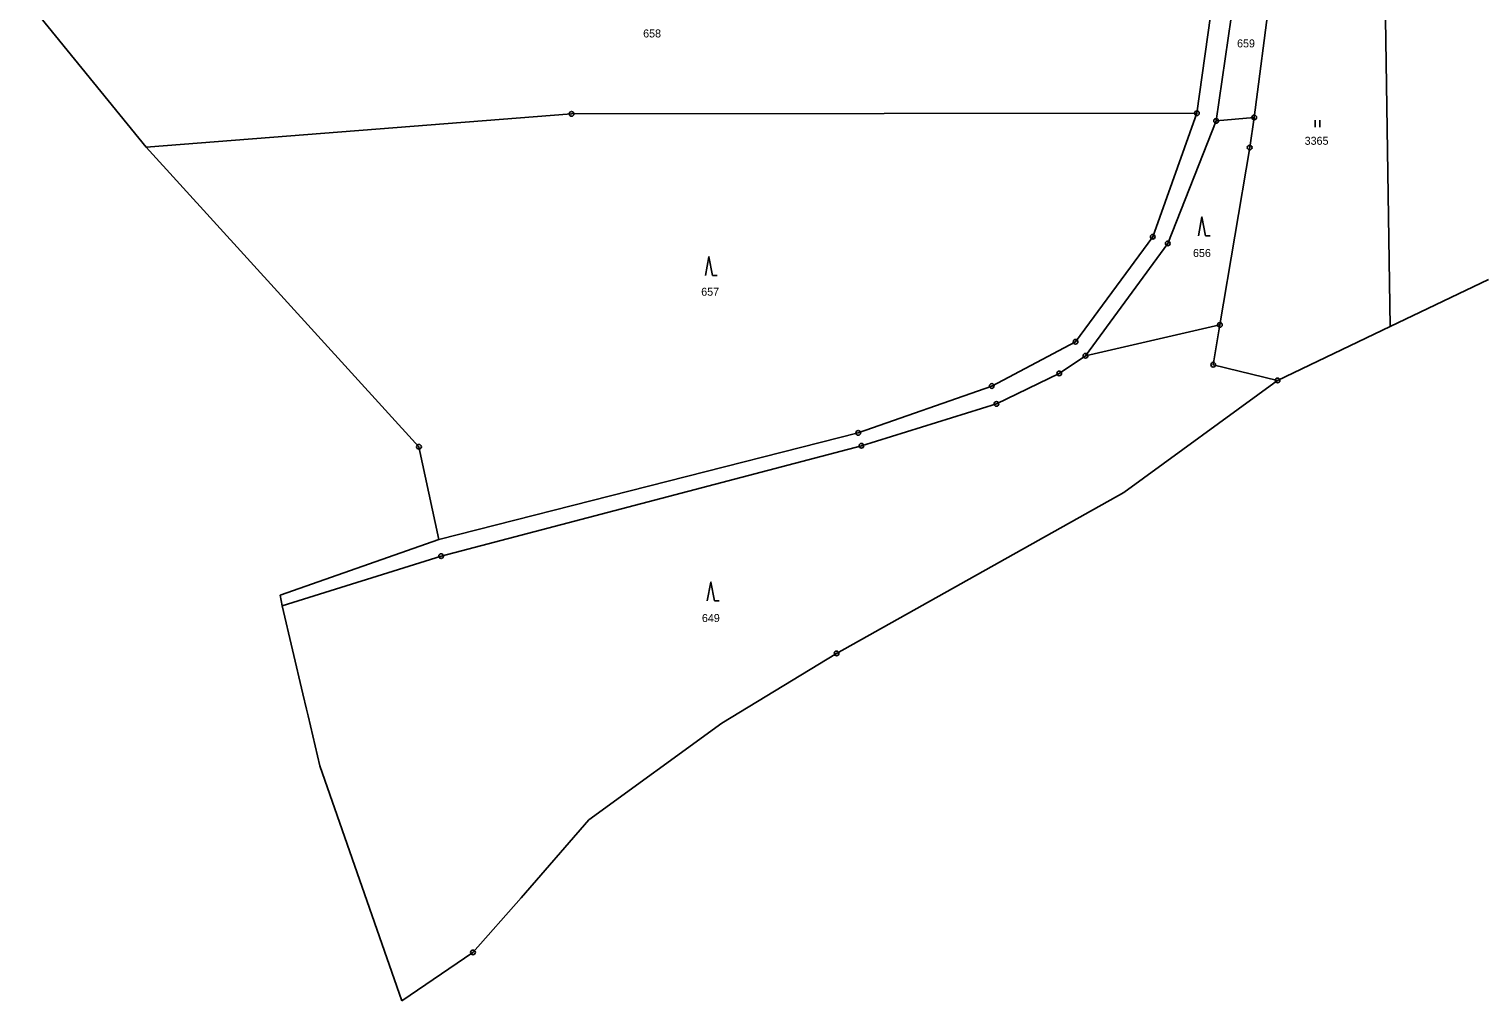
# Model space of a CAD drawing. Extents: x -618848 to -615803, y -1044450 to -1042254.
# Drawn here: x -618808.6 to -618500.4, y -1044247.6 to -1044041.1 of the extents above; entities that cross this region are included whole.
import ezdxf
from ezdxf.enums import TextEntityAlignment as Align

# ---------------------------------------------------------------- set-up
doc = ezdxf.new("R2010")
doc.units = 0
doc.header["$LTSCALE"] = 0.68
for name, color, linetype, lineweight in [('1', 7, 'Continuous', 25), ('3', 7, 'Continuous', 25), ('8', 7, 'Continuous', 25)]:
    doc.layers.add(name, color=color, linetype=linetype, lineweight=lineweight)
doc.layers.add('2', color=7, linetype='Continuous')

msp = doc.modelspace()

# ---------------------------------------------------------------- linework, layer by layer
at = {"layer": '1'}
for p, q in [((-618521.01, -1044002.05), (-618519.5, -1044104.29)), ((-618560.52, -1044058.97), (-618555.21, -1044021.21)), ((-618556.45, -1044060.6), (-618550.93, -1044022.46)), ((-618543.72, -1044024.32), (-618548.36, -1044059.86)), ((-618808.59, -1044035.66), (-618783.68, -1044066.18)), ((-618783.68, -1044066.18), (-618693.34, -1044059.1)), ((-618693.34, -1044059.1), (-618560.52, -1044058.97)), ((-618560.52, -1044058.97), (-618569.91, -1044085.21)), ((-618566.73, -1044086.63), (-618556.45, -1044060.6)), ((-618556.45, -1044060.6), (-618548.36, -1044059.86)), ((-618548.36, -1044059.86), (-618549.32, -1044066.26)), ((-618783.68, -1044066.18), (-618725.76, -1044129.84)), ((-618549.32, -1044066.26), (-618555.64, -1044103.94)), ((-618569.91, -1044085.21), (-618586.31, -1044107.53)), ((-618584.19, -1044110.49), (-618566.73, -1044086.63)), ((-618498.61, -1044094.27), (-618519.5, -1044104.29)), ((-618584.19, -1044110.49), (-618555.64, -1044103.94)), ((-618555.64, -1044103.94), (-618557.07, -1044112.39)), ((-618543.38, -1044115.75), (-618519.5, -1044104.29)), ((-618586.31, -1044107.53), (-618604.1, -1044116.92)), ((-618589.77, -1044114.24), (-618584.19, -1044110.49)), ((-618557.07, -1044112.39), (-618543.38, -1044115.75)), ((-618604.1, -1044116.92), (-618632.46, -1044126.87)), ((-618603.1, -1044120.73), (-618589.77, -1044114.24)), ((-618576.05, -1044139.52), (-618543.38, -1044115.75)), ((-618631.79, -1044129.6), (-618603.1, -1044120.73)), ((-618632.46, -1044126.87), (-618721.57, -1044149.5)), ((-618725.76, -1044129.84), (-618721.57, -1044149.5)), ((-618721.07, -1044153.07), (-618631.79, -1044129.6)), ((-618755.25, -1044161.39), (-618721.57, -1044149.5)), ((-618754.79, -1044163.6), (-618721.07, -1044153.07)), ((-618755.25, -1044161.39), (-618754.79, -1044163.6)), ((-618754.79, -1044163.6), (-618750.4, -1044182.33)), ((-618750.4, -1044182.33), (-618749.64, -1044185.58)), ((-618749.64, -1044185.58), (-618749.3, -1044187.02)), ((-618749.3, -1044187.02), (-618746.81, -1044197.63)), ((-618689.7, -1044209.09), (-618661.45, -1044188.56)), ((-618746.81, -1044197.63), (-618729.38, -1044247.57)), ((-618689.7, -1044209.09), (-618704.07, -1044225.65)), ((-618704.07, -1044225.65), (-618714.29, -1044237.24)), ((-618714.29, -1044237.24), (-618729.38, -1044247.57))]:
    msp.add_line(p, q, dxfattribs=at)
msp.add_lwpolyline([(-618661.45, -1044188.56), (-618637.06, -1044173.73), (-618576.05, -1044139.52)], dxfattribs=at)
at = {"layer": '3'}
for p, q in [((-618535.401, -1044061.91), (-618535.401, -1044060.41)), ((-618534.4, -1044061.91), (-618534.4, -1044060.41)), ((-618558.7, -1044085.01), (-618557.704, -1044085.01)), ((-618663.42, -1044093.45), (-618662.424, -1044093.45)), ((-618663.02, -1044162.56), (-618662.024, -1044162.56))]:
    msp.add_line(p, q, dxfattribs=at)
for points in [[(-618558.7, -1044085.01), (-618559.45, -1044081.01), (-618560.2, -1044085.01)], [(-618663.42, -1044093.45), (-618664.17, -1044089.45), (-618664.92, -1044093.45)], [(-618663.02, -1044162.56), (-618663.77, -1044158.56), (-618664.52, -1044162.56)]]:
    msp.add_lwpolyline(points, dxfattribs=at)
at = {"layer": '8'}
for centre, radius in [((-618693.34, -1044059.0999), 0.5), ((-618560.52, -1044058.9699), 0.5), ((-618693.34, -1044059.0999), 0.0303), ((-618560.52, -1044058.9699), 0.0303), ((-618556.45, -1044060.5999), 0.5), ((-618556.45, -1044060.5999), 0.0303), ((-618548.36, -1044059.8599), 0.5), ((-618548.36, -1044059.8599), 0.0303), ((-618549.32, -1044066.2599), 0.5), ((-618549.32, -1044066.2599), 0.0303), ((-618569.91, -1044085.2099), 0.5), ((-618569.91, -1044085.2099), 0.0303), ((-618566.73, -1044086.6299), 0.5), ((-618566.73, -1044086.6299), 0.0303), ((-618555.64, -1044103.9399), 0.5), ((-618555.64, -1044103.9399), 0.0303), ((-618586.31, -1044107.5299), 0.5), ((-618586.31, -1044107.5299), 0.0303), ((-618584.19, -1044110.4899), 0.5), ((-618584.19, -1044110.4899), 0.0303), ((-618589.77, -1044114.2399), 0.5), ((-618557.07, -1044112.3899), 0.5), ((-618557.07, -1044112.3899), 0.0303), ((-618604.1, -1044116.9199), 0.5), ((-618604.1, -1044116.9199), 0.0303), ((-618589.77, -1044114.2399), 0.0303), ((-618543.38, -1044115.7499), 0.5), ((-618543.38, -1044115.7499), 0.0303), ((-618603.1, -1044120.7299), 0.5), ((-618603.1, -1044120.7299), 0.0303), ((-618632.46, -1044126.8699), 0.5), ((-618725.76, -1044129.8399), 0.5), ((-618632.46, -1044126.8699), 0.0303), ((-618631.79, -1044129.5999), 0.5), ((-618725.76, -1044129.8399), 0.0303), ((-618631.79, -1044129.5999), 0.0303), ((-618721.07, -1044153.0699), 0.5), ((-618721.07, -1044153.0699), 0.0303), ((-618637.06, -1044173.7299), 0.5), ((-618637.06, -1044173.7299), 0.0303), ((-618714.29, -1044237.2399), 0.5), ((-618714.29, -1044237.2399), 0.0303)]:
    msp.add_circle(centre, radius, dxfattribs=at)

# ---------------------------------------------------------------- texts
at = {"layer": '2'}
for s, p in [('658', (-618676.249, -1044042.875)), ('659', (-618550.099, -1044044.985)), ('656', (-618559.459, -1044089.515)), ('657', (-618663.919, -1044097.745)), ('649', (-618663.769, -1044167.065))]:
    msp.add_text(s, height=1.7, dxfattribs=at).set_placement(p, align=Align.CENTER)
msp.add_text('3365', height=1.7, dxfattribs=at).set_placement((-618537.64, -1044065.675))

doc.saveas('drawing.dxf')
